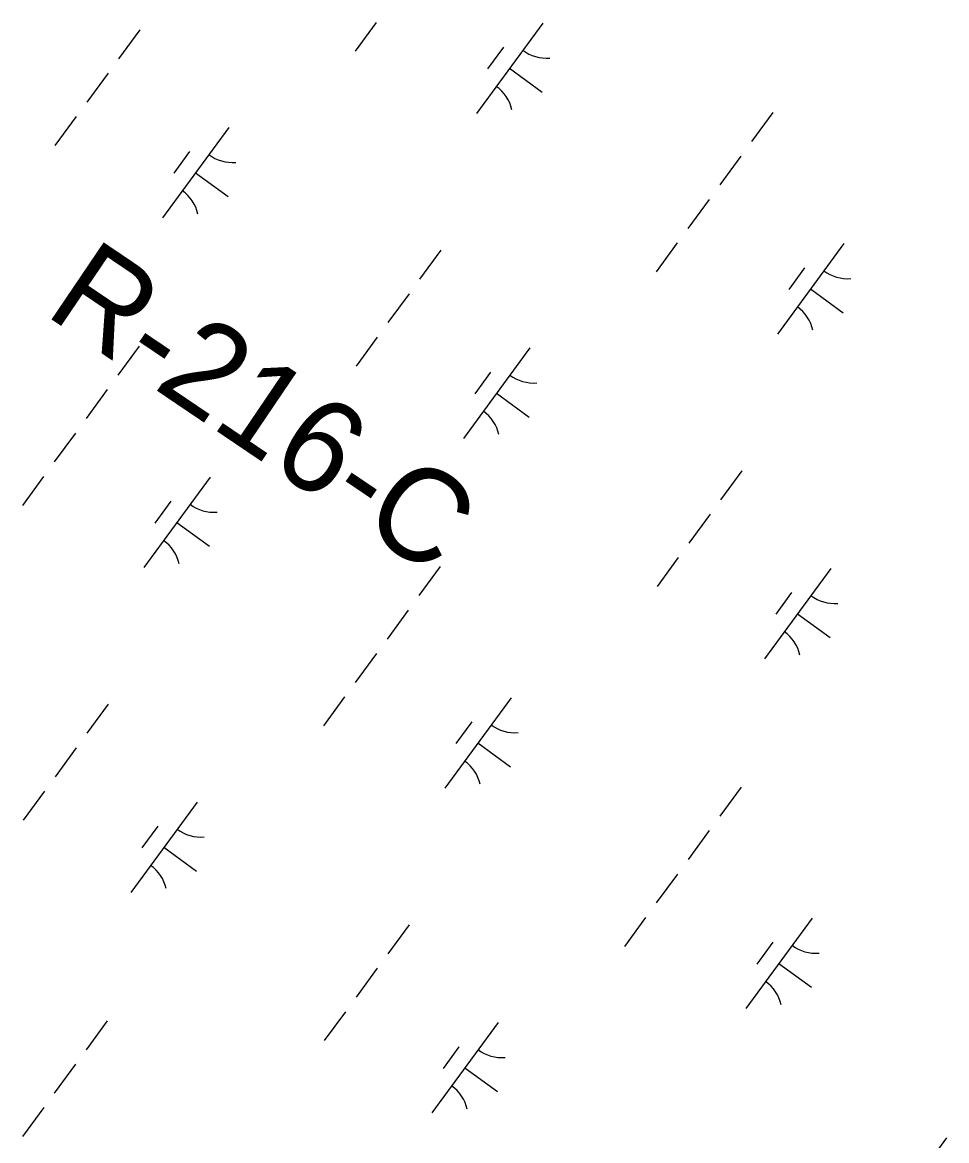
# Model space of a CAD drawing. Extents: x 3905714 to 3926767, y 183354 to 205755.
# Drawn here: x 3915129 to 3915541, y 187928.7 to 188427.2 of the extents above; entities that cross this region are included whole.
import ezdxf

# ---------------------------------------------------------------- set-up
doc = ezdxf.new("R2010")
doc.units = 0
doc.layers.add('V-RIVR-RANG-IDEN', color=7, linetype='Continuous')
doc.layers.add('V-WETL-SWMP', color=7, linetype='Continuous')

msp = doc.modelspace()

# ---------------------------------------------------------------- linework, layer by layer
at = {"layer": 'V-WETL-SWMP'}
for p, q in [((3915181.35, 188423.93), (3915171.89, 188411.02)), ((3915286.76, 188427.22), (3915277.31, 188414.32)), ((3915360.95, 188426.89), (3915331.4, 188386.56)), ((3915343.49, 188416.13), (3915336.4, 188406.45)), ((3915167.17, 188404.57), (3915157.71, 188391.66)), ((3915346.17, 188406.73), (3915360.69, 188396.09)), ((3915152.98, 188385.21), (3915143.53, 188372.3)), ((3915463.49, 188387), (3915454.04, 188374.09)), ((3915220.99, 188380.38), (3915191.44, 188340.05)), ((3915203.54, 188369.61), (3915196.45, 188359.93)), ((3915449.31, 188367.64), (3915439.85, 188354.73)), ((3915206.22, 188360.21), (3915220.74, 188349.57)), ((3915435.13, 188348.28), (3915425.67, 188335.37)), ((3915420.94, 188328.92), (3915411.49, 188316.01)), ((3915495.13, 188328.59), (3915465.58, 188288.25)), ((3915315.53, 188325.62), (3915306.07, 188312.72)), ((3915477.67, 188317.82), (3915470.58, 188308.14)), ((3915480.35, 188308.42), (3915494.87, 188297.78)), ((3915301.35, 188306.26), (3915291.89, 188293.36)), ((3915287.16, 188286.9), (3915277.71, 188274)), ((3915181, 188282.87), (3915171.54, 188269.96)), ((3915355.17, 188282.07), (3915325.62, 188241.74)), ((3915337.72, 188271.31), (3915330.63, 188261.63)), ((3915166.82, 188263.51), (3915157.36, 188250.6)), ((3915340.4, 188261.91), (3915354.92, 188251.27)), ((3915152.63, 188244.15), (3915143.18, 188231.24)), ((3915138.45, 188224.79), (3915128.99, 188211.88)), ((3915212.63, 188224.46), (3915183.08, 188184.12)), ((3915449.71, 188227.32), (3915440.25, 188214.41)), ((3915195.18, 188213.69), (3915188.09, 188204.01)), ((3915197.86, 188204.29), (3915212.38, 188193.65)), ((3915435.53, 188207.96), (3915426.07, 188195.05)), ((3915421.34, 188188.6), (3915411.89, 188175.69)), ((3915315.18, 188184.56), (3915305.72, 188171.65)), ((3915489.35, 188183.77), (3915459.8, 188143.43)), ((3915471.9, 188173), (3915464.8, 188163.32)), ((3915301, 188165.2), (3915291.54, 188152.29)), ((3915474.57, 188163.6), (3915489.09, 188152.96)), ((3915286.81, 188145.84), (3915277.36, 188132.93)), ((3915272.63, 188126.48), (3915263.17, 188113.57)), ((3915346.81, 188126.15), (3915317.26, 188085.82)), ((3915167.22, 188123.19), (3915157.76, 188110.28)), ((3915329.36, 188115.38), (3915322.27, 188105.7)), ((3915153.03, 188103.83), (3915143.58, 188090.92)), ((3915332.04, 188105.98), (3915346.56, 188095.35)), ((3915138.85, 188084.47), (3915129.39, 188071.56)), ((3915449.36, 188086.25), (3915439.9, 188073.35)), ((3915206.86, 188079.64), (3915177.31, 188039.3)), ((3915189.4, 188068.87), (3915182.31, 188059.19)), ((3915435.17, 188066.89), (3915425.72, 188053.99)), ((3915192.08, 188059.47), (3915206.6, 188048.83)), ((3915420.99, 188047.53), (3915411.53, 188034.63)), ((3915301.39, 188024.88), (3915291.94, 188011.97)), ((3915406.81, 188028.17), (3915397.35, 188015.27)), ((3915480.99, 188027.85), (3915451.44, 187987.51)), ((3915463.54, 188017.08), (3915456.45, 188007.4)), ((3915287.21, 188005.52), (3915277.75, 187992.61)), ((3915466.21, 188007.68), (3915480.74, 187997.04)), ((3915273.03, 187986.16), (3915263.57, 187973.25)), ((3915166.86, 187982.12), (3915157.41, 187969.22)), ((3915341.04, 187981.33), (3915311.49, 187941)), ((3915323.58, 187970.56), (3915316.49, 187960.88)), ((3915152.68, 187962.76), (3915143.22, 187949.86)), ((3915326.26, 187961.16), (3915340.78, 187950.53)), ((3915138.5, 187943.4), (3915129.04, 187930.5)), ((3915540.99, 187929.87), (3915531.53, 187916.96))]:
    msp.add_line(p, q, dxfattribs=at)
for centre, start, end in [((3915362.69, 188428.87), 233, 274.5436), ((3915330.04, 188384.31), 13, 54.5436), ((3915222.73, 188382.35), 233, 274.5436), ((3915190.08, 188337.79), 13, 54.5436), ((3915496.87, 188330.56), 233, 274.5436), ((3915464.22, 188286), 13, 54.5436), ((3915356.91, 188284.05), 233, 274.5436), ((3915324.26, 188239.48), 13, 54.5436), ((3915214.37, 188226.43), 233, 274.5436), ((3915181.72, 188181.87), 13, 54.5436), ((3915491.09, 188185.74), 233, 274.5436), ((3915458.44, 188141.18), 13, 54.5436), ((3915348.55, 188128.13), 233, 274.5436), ((3915315.9, 188083.56), 13, 54.5436), ((3915208.6, 188081.61), 233, 274.5436), ((3915175.95, 188037.05), 13, 54.5436), ((3915482.73, 188029.82), 233, 274.5436), ((3915450.08, 187985.26), 13, 54.5436), ((3915342.78, 187983.3), 233, 274.5436), ((3915310.13, 187938.74), 13, 54.5436)]:
    msp.add_arc(centre, 17.62, start, end, dxfattribs=at)

# ---------------------------------------------------------------- texts
at = {"layer": 'V-RIVR-RANG-IDEN'}
msp.add_text('R-216-C', height=41.5, rotation=325.9327, dxfattribs=at).set_placement((3915138.21, 188297.33))

doc.saveas('drawing.dxf')
